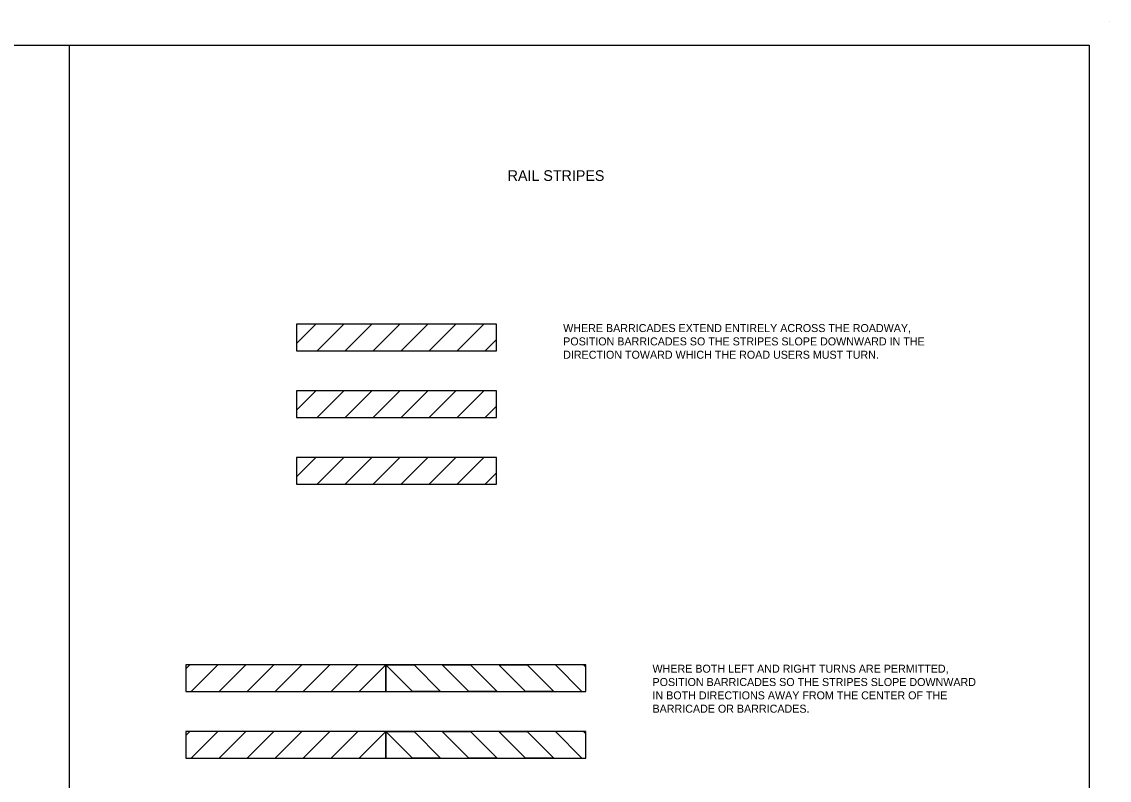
# Model space of a CAD drawing. Extents: x 49991.4 to 50021, y 49987.6 to 50011.4.
# Drawn here: x 50008.75 to 50016.9, y 49993.49 to 49999.18 of the extents above; entities that cross this region are included whole.
import ezdxf

# ---------------------------------------------------------------- set-up
doc = ezdxf.new("R2010")
doc.units = 0
doc.layers.add('Level 1', color=7, linetype='Continuous')
doc.layers.add('Level 2', color=7, linetype='Continuous')

msp = doc.modelspace()

# ---------------------------------------------------------------- linework, layer by layer
at = {"layer": 'Level 1'}
for p, q in [((50016.9001, 49999.1756), (50016.9001, 49999.1756)), ((50011.6752, 49994.153), (50011.4756, 49994.353)), ((50011.6752, 49994.153), (50011.4756, 49994.353)), ((50011.8872, 49994.153), (50011.6876, 49994.353)), ((50011.6876, 49994.353), (50011.8872, 49994.153)), ((50012.0991, 49994.153), (50011.8995, 49994.353)), ((50012.0991, 49994.153), (50011.8995, 49994.353)), ((50012.3111, 49994.153), (50012.1115, 49994.353)), ((50012.1115, 49994.353), (50012.3111, 49994.153)), ((50012.523, 49994.153), (50012.3234, 49994.353)), ((50012.523, 49994.153), (50012.3234, 49994.353)), ((50012.735, 49994.153), (50012.5354, 49994.353)), ((50012.5354, 49994.353), (50012.735, 49994.153)), ((50011.6752, 49993.653), (50011.4756, 49993.853)), ((50011.8872, 49993.653), (50011.6876, 49993.853)), ((50011.6876, 49993.853), (50011.8872, 49993.653)), ((50012.0991, 49993.653), (50011.8995, 49993.853)), ((50012.0991, 49993.653), (50011.8995, 49993.853)), ((50012.3111, 49993.653), (50012.1115, 49993.853)), ((50012.1115, 49993.853), (50012.3111, 49993.653)), ((50012.523, 49993.653), (50012.3234, 49993.853)), ((50012.523, 49993.653), (50012.3234, 49993.853)), ((50012.735, 49993.653), (50012.5354, 49993.853)), ((50012.5354, 49993.853), (50012.735, 49993.653))]:
    msp.add_line(p, q, dxfattribs=at)
for points in [[(49999.3835, 49998.9992), (50016.7501, 49998.9992), (50016.7501, 49987.7988), (49999.3835, 49987.7988)], [(50012.3059, 49996.9079), (50010.8059, 49996.9079), (50010.8059, 49996.7079), (50012.3059, 49996.7079)], [(50012.3059, 49996.4079), (50010.8059, 49996.4079), (50010.8059, 49996.2079), (50012.3059, 49996.2079)], [(50012.3059, 49995.9079), (50010.8059, 49995.9079), (50010.8059, 49995.7079), (50012.3059, 49995.7079)], [(50011.4756, 49994.353), (50009.9756, 49994.353), (50009.9756, 49994.153), (50011.4756, 49994.153)], [(50012.9756, 49994.353), (50011.4756, 49994.353), (50011.4756, 49994.153), (50012.9756, 49994.153)], [(50011.4756, 49993.853), (50009.9756, 49993.853), (50009.9756, 49993.653), (50011.4756, 49993.653)], [(50012.9756, 49993.853), (50011.4756, 49993.853), (50011.4756, 49993.653), (50012.9756, 49993.653)]]:
    msp.add_lwpolyline(points, close=True, dxfattribs=at)
for points in [[(50011.4756, 49994.353), (50011.6876, 49994.353)], [(50011.8995, 49994.353), (50012.1115, 49994.353)], [(50012.3234, 49994.353), (50012.5354, 49994.353)], [(50011.8872, 49994.153), (50011.6752, 49994.153)], [(50012.3111, 49994.153), (50012.0991, 49994.153)], [(50012.735, 49994.153), (50012.523, 49994.153)], [(50011.4756, 49993.853), (50011.6876, 49993.853)], [(50011.8995, 49993.853), (50012.1115, 49993.853)], [(50012.3234, 49993.853), (50012.5354, 49993.853)], [(50011.8872, 49993.653), (50011.6752, 49993.653)], [(50012.3111, 49993.653), (50012.0991, 49993.653)], [(50012.735, 49993.653), (50012.523, 49993.653)]]:
    msp.add_lwpolyline(points, dxfattribs=at)
at = {"layer": 'Level 2'}
for p, q in [((50009.1021, 49998.9973), (50009.1021, 49987.7969)), ((50011.1606, 49996.9079), (50010.9606, 49996.7079)), ((50012.2106, 49996.9079), (50012.0106, 49996.7079)), ((50012.2206, 49996.7079), (50012.3059, 49996.7932)), ((50011.1606, 49996.4079), (50010.9606, 49996.2079)), ((50012.2106, 49996.4079), (50012.0106, 49996.2079)), ((50012.2206, 49996.2079), (50012.3059, 49996.2932)), ((50011.1606, 49995.9079), (50010.9606, 49995.7079)), ((50012.2106, 49995.9079), (50012.0106, 49995.7079)), ((50012.2206, 49995.7079), (50012.3059, 49995.7932)), ((50010.0056, 49994.353), (50009.9756, 49994.323)), ((50010.2156, 49994.353), (50010.0156, 49994.153)), ((50010.2156, 49994.353), (50010.0156, 49994.153)), ((50010.4256, 49994.353), (50010.2256, 49994.153)), ((50010.4256, 49994.353), (50010.2256, 49994.153)), ((50010.6356, 49994.353), (50010.4356, 49994.153)), ((50010.6356, 49994.353), (50010.4356, 49994.153)), ((50010.8456, 49994.353), (50010.6456, 49994.153)), ((50010.8456, 49994.353), (50010.6456, 49994.153)), ((50011.0556, 49994.353), (50010.8556, 49994.153)), ((50011.2656, 49994.353), (50011.0656, 49994.153)), ((50011.4756, 49994.353), (50011.2756, 49994.153)), ((50011.4756, 49994.353), (50011.6752, 49994.153))]:
    msp.add_line(p, q, dxfattribs=at)
for points in [[(50010.8059, 49996.7632), (50010.8059, 49996.7079), (50010.9606, 49996.7079), (50011.1606, 49996.9079), (50010.9506, 49996.9079), (50010.8059, 49996.7632)], [(50011.1706, 49996.7079), (50011.3806, 49996.7079), (50011.5806, 49996.9079), (50011.3706, 49996.9079), (50011.1706, 49996.7079)], [(50011.5906, 49996.7079), (50011.8006, 49996.7079), (50012.0006, 49996.9079), (50011.7906, 49996.9079), (50011.5906, 49996.7079)], [(50012.3059, 49996.7932), (50012.3059, 49996.9079), (50012.2106, 49996.9079), (50012.0106, 49996.7079), (50012.2206, 49996.7079), (50012.3059, 49996.7932)], [(50010.8059, 49996.2632), (50010.8059, 49996.2079), (50010.9606, 49996.2079), (50011.1606, 49996.4079), (50010.9506, 49996.4079), (50010.8059, 49996.2632)], [(50011.1706, 49996.2079), (50011.3806, 49996.2079), (50011.5806, 49996.4079), (50011.3706, 49996.4079), (50011.1706, 49996.2079)], [(50011.5906, 49996.2079), (50011.8006, 49996.2079), (50012.0006, 49996.4079), (50011.7906, 49996.4079), (50011.5906, 49996.2079)], [(50012.3059, 49996.2932), (50012.3059, 49996.4079), (50012.2106, 49996.4079), (50012.0106, 49996.2079), (50012.2206, 49996.2079), (50012.3059, 49996.2932)], [(50010.8059, 49995.7632), (50010.8059, 49995.7079), (50010.9606, 49995.7079), (50011.1606, 49995.9079), (50010.9506, 49995.9079), (50010.8059, 49995.7632)], [(50011.1706, 49995.7079), (50011.3806, 49995.7079), (50011.5806, 49995.9079), (50011.3706, 49995.9079), (50011.1706, 49995.7079)], [(50011.5906, 49995.7079), (50011.8006, 49995.7079), (50012.0006, 49995.9079), (50011.7906, 49995.9079), (50011.5906, 49995.7079)], [(50012.3059, 49995.7932), (50012.3059, 49995.9079), (50012.2106, 49995.9079), (50012.0106, 49995.7079), (50012.2206, 49995.7079), (50012.3059, 49995.7932)], [(50009.9756, 49994.323), (50009.9756, 49994.153), (50010.0156, 49994.153), (50010.2156, 49994.353), (50010.0056, 49994.353), (50009.9756, 49994.323)], [(50010.2256, 49994.153), (50010.4356, 49994.153), (50010.6356, 49994.353), (50010.4256, 49994.353), (50010.2256, 49994.153)], [(50010.6456, 49994.153), (50010.8556, 49994.153), (50011.0556, 49994.353), (50010.8456, 49994.353), (50010.6456, 49994.153)], [(50011.0656, 49994.153), (50011.2756, 49994.153), (50011.4756, 49994.353), (50011.2656, 49994.353), (50011.0656, 49994.153)], [(50012.9756, 49994.3347), (50012.9573, 49994.353), (50012.7473, 49994.353), (50012.9469, 49994.153), (50012.9756, 49994.153), (50012.9756, 49994.3347)], [(50009.9756, 49993.823), (50009.9756, 49993.653), (50010.0156, 49993.653), (50010.2156, 49993.853), (50010.0056, 49993.853), (50009.9756, 49993.823)], [(50010.2256, 49993.653), (50010.4356, 49993.653), (50010.6356, 49993.853), (50010.4256, 49993.853), (50010.2256, 49993.653)], [(50010.6456, 49993.653), (50010.8556, 49993.653), (50011.0556, 49993.853), (50010.8456, 49993.853), (50010.6456, 49993.653)], [(50011.0656, 49993.653), (50011.2756, 49993.653), (50011.4756, 49993.853), (50011.2656, 49993.853), (50011.0656, 49993.653)], [(50012.9756, 49993.8347), (50012.9573, 49993.853), (50012.7473, 49993.853), (50012.9469, 49993.653), (50012.9756, 49993.653), (50012.9756, 49993.8347)]]:
    msp.add_lwpolyline(points, dxfattribs=at)

# ---------------------------------------------------------------- texts
for s, height, p in [('RAIL STRIPES', 0.08, (50012.3895, 49997.9818)), ('WHERE BARRICADES EXTEND ENTIRELY ACROSS THE ROADWAY,', 0.06, (50012.8059, 49996.8479)), ('POSITION BARRICADES SO THE STRIPES SLOPE DOWNWARD IN THE', 0.06, (50012.8059, 49996.7479)), ('DIRECTION TOWARD WHICH THE ROAD USERS MUST TURN.', 0.06, (50012.8059, 49996.6479)), ('WHERE BOTH LEFT AND RIGHT TURNS ARE PERMITTED,', 0.06, (50013.4756, 49994.293)), ('POSITION BARRICADES SO THE STRIPES SLOPE DOWNWARD', 0.06, (50013.4756, 49994.193)), ('IN BOTH DIRECTIONS AWAY FROM THE CENTER OF THE ', 0.06, (50013.4756, 49994.093)), ('BARRICADE OR BARRICADES.', 0.06, (50013.4756, 49993.993))]:
    msp.add_text(s, height=height, dxfattribs=at).set_placement(p)

doc.saveas('drawing.dxf')
